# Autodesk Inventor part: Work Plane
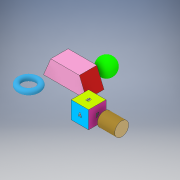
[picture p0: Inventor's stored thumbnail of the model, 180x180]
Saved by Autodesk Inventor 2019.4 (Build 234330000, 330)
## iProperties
Created: 2018-06
Part Number: Work Plane
Material: Generic
Document SubType Name: Modeling
Designer: Power User
Density: 1 g/cm^3
Appearance: Default
Author: Power User
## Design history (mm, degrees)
sketch "Sketch1"
  geometry: L1 (0, 0)-(50, 0); L2 (50, 0)-(50, -50); L3 (50, -50)-(0, -50); L4 (0, -50)-(0, 0)
  constraints: 8 end point, 2 parallel, 1 horizontal, 1 perpendicular
  dimensions: "d0" = 50 distance of L1.end L2.end; "d1" = 50 distance of L2.end L3.end
extrude "Extrusion1" new body sketch "Sketch1" distance "d2" = 50; taper "d3" = 0 deg
workplane "Work Plane1"
sketch "Sketch2"
  geometry: L1 (0, 50)-(50, 50) reference; L2 (50, 0)-(50, 50) reference; C1 r 20 at (25, 25); 3 further points
  constraints: 2 midpoint, 1 centre point, 1 horizontal alignment, 1 vertical alignment
  dimensions: "d5" = 40 diameter of C1
extrude "Extrusion2" join sketch "Sketch2" distance "d6" = 50; taper "d7" = 0 deg
sketch "Sketch3"
  geometry: L1 (-172.16, 49.98)-(-172.16, 11.482); C1 r 7.5 at (-197.16, 26.587); 1 further point
  constraints: 2 end point, 1 centre point, 1 vertical
  dimensions: "d8" = 15 diameter of C1; "d9" = 50 diameter of C1.centre L1
revolve "Revolution1" sketch "Sketch3" stored, may be unused: angle "d10" = 90 deg
workplane "Work Plane2"
sketch "Sketch4"
  geometry: L1 (-98.807, 58.325)-(-98.807, 8.325); A1 r 25 centre (-98.807, 33.325) between (-98.807, 58.325) and (-98.807, 8.325); 1 further point
  constraints: 2 end point, 2 point on circle, 1 centre point, 1 vertical
  dimensions: "d12" = 50 diameter of A1
revolve "Revolution2" sketch "Sketch4" stored, may be unused: angle "d13" = 90 deg
workplane "Work Plane3"
sketch "Sketch5"
  geometry: L1 (-192.037, 9.98)-(-171.326, 59.98); L2 (-171.326, 59.98)-(-89.041, 59.98); L3 (-89.041, 59.98)-(-68.33, 9.98); L4 (-68.33, 9.98)-(-192.037, 9.98); L5 (-130.184, 59.98)-(-130.184, 9.98); 1 further point
  constraints: 10 end point, 2 midpoint, 1 horizontal, 1 parallel, 1 perpendicular, 1 other
  dimensions: "d15" = 50 distance between parallel lines of L4 L2; "d16" = 45 deg angle of L3 L1
extrude "Extrusion3" join sketch "Sketch5" stored distance "d17" = 50; taper "d18" = 0 deg
sketch "Sketch6"
  geometry: L1 (15, 35)-(35, 35); L2 (35, 35)-(35, 15); L3 (35, 15)-(15, 15); L4 (15, 15)-(15, 35); L5 (0, 50)-(50, 50) reference; L6 (0, 0)-(0, 50) reference; 5 further points
  constraints: 4 midpoint, 1 horizontal alignment, 1 vertical alignment, 2 other
  dimensions: "d19" = 20 distance of L1.start L1.end; "d20" = 20 distance of L1.end L2.end
emboss "Emboss1" sketch "Sketch6" dims "d0" = 50, "d1" = 50, "d21" = 0.2, "d22" = 0
sketch "Sketch7"
  geometry: L1 (-35, 35)-(-15, 35); L2 (-15, 35)-(-15, 15); L3 (-15, 15)-(-35, 15); L4 (-35, 15)-(-35, 35); L5 (0, 50)-(-50, 50) reference; L6 (-50, 50)-(-50, 0) reference; 5 further points
  constraints: 4 midpoint, 1 horizontal alignment, 1 vertical alignment, 2 other
  dimensions: "d23" = 20 distance of L1.start L1.end; "d24" = 20 distance of L3.end L1.start
emboss "Emboss2" sketch "Sketch7" dims "d0" = 50, "d1" = 50, "d25" = 0.2, "d26" = 0
sketch "Sketch8"
  geometry: L1 (15, 35)-(35, 35); L2 (35, 35)-(35, 15); L3 (35, 15)-(15, 15); L4 (15, 15)-(15, 35); L5 (0, 0)-(0, 50) reference; L6 (0, 50)-(50, 50) reference; 4 further points
  constraints: 4 midpoint, 1 horizontal alignment, 1 vertical alignment, 2 other
  dimensions: "d27" = 20 distance of L1.start L1.end; "d28" = 20 distance of L3.end L1.start
emboss "Emboss3" sketch "Sketch8" dims "d0" = 50, "d1" = 50, "d29" = 0.2, "d30" = 0
sketch "Sketch9"
  geometry: L1 (-11.219, -35.018)-(-35.694, -35.018); L2 (-35.694, -35.018)-(-35.694, -14.982); L3 (-35.694, -14.982)-(-11.219, -14.982); L4 (-11.219, -14.982)-(-11.219, -35.018); L5 (0, -50)-(0, 0) reference; 4 further points
  constraints: 3 midpoint, 1 horizontal alignment, 1 vertical alignment, 2 other
emboss "Emboss4" sketch "Sketch9" dims "d0" = 50, "d1" = 50, "d31" = 0.2, "d32" = 0
sketch "Sketch10"
  geometry: L1 (15, 35)-(35, 35); L2 (35, 35)-(35, 15); L3 (35, 15)-(15, 15); L4 (15, 15)-(15, 35); L5 (0, 50)-(50, 50) reference; L6 (0, 0)-(0, 50) reference; 5 further points
  constraints: 4 midpoint, 1 horizontal alignment, 1 vertical alignment, 2 other
  dimensions: "d33" = 20 distance of L1.start L1.end; "d34" = 20 distance of L3.end L1.start
emboss "Emboss5" sketch "Sketch10" dims "d0" = 50, "d1" = 50, "d35" = 0.2, "d36" = 0
sketch "Sketch11"
  geometry: L1 (15, 35)-(35, 35); L2 (35, 35)-(35, 15); L3 (35, 15)-(15, 15); L4 (15, 15)-(15, 35); L5 (0, 0)-(0, 50) reference; L6 (0, 50)-(50, 50) reference; 4 further points
  constraints: 4 midpoint, 1 horizontal alignment, 1 vertical alignment, 2 other
  dimensions: "d37" = 20 distance of L1.start L1.end; "d38" = 20 distance of L1.end L2.end
emboss "Emboss6" sketch "Sketch11" dims "d0" = 50, "d1" = 50, "d39" = 0.2, "d40" = 0
body "Solid1"
other parameters: "d14" = -87.5
